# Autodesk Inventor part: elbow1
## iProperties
Shininess: 64.0
Length Units: 11269
Angle Units: 11279
Time Units: 11290
Mass Units: 11283
Length Display Precision: 3
Angle Display Precision: 2
Compacted: True
Part Number: elbow1
Document SubType Name: Modeling
Created: 2003-07
Designer: JB
Density: 0.0
Volumn: 0.0
Area: 0.0
PropertySet Name: Model Information
Control State: 0
Master: False
Checked Out: False
Author: JB
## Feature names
1. Sweep1
